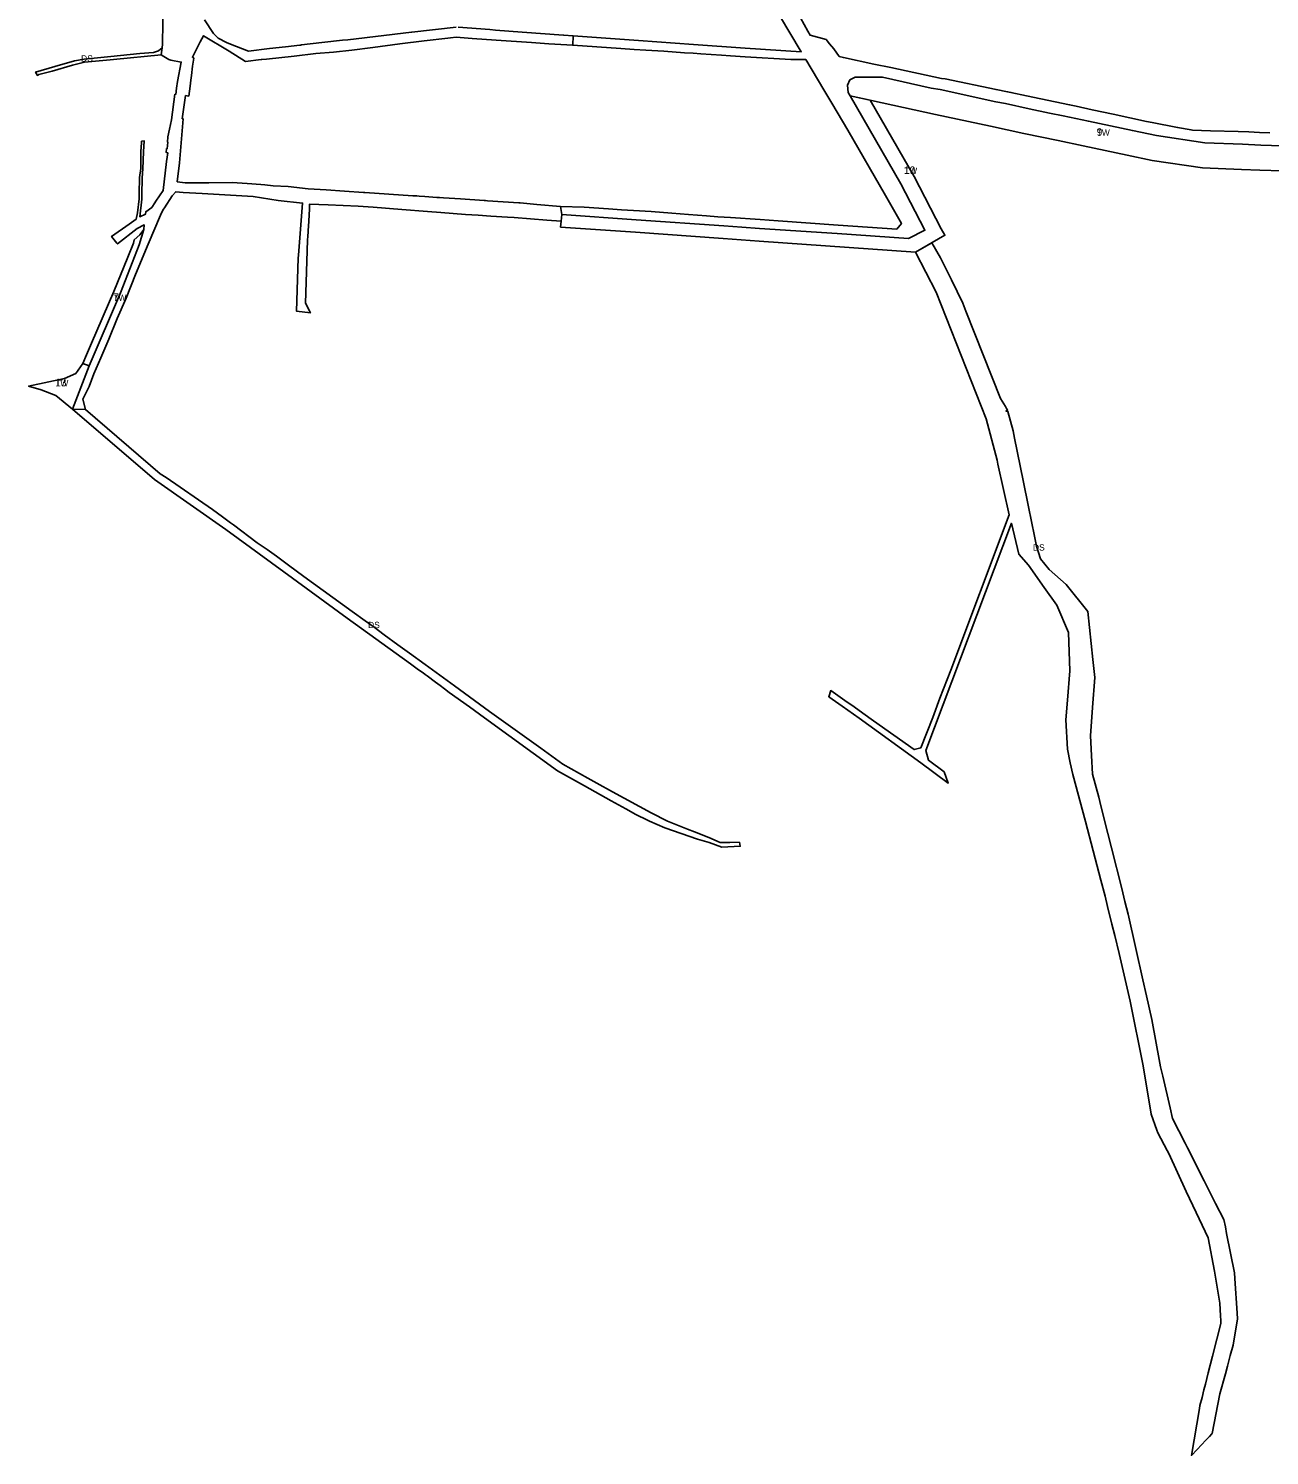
# Model space of a CAD drawing. Extents: x -540396 to -537847, y -1162344 to -1159959.
# Drawn here: x -540086 to -539100, y -1162344 to -1161210 of the extents above; entities that cross this region are included whole.
import ezdxf

# ---------------------------------------------------------------- set-up
doc = ezdxf.new("R2010")
doc.units = 0
for name, color, linetype in [('90320013', 7, 'Continuous'), ('90390023', 7, 'Continuous'), ('90450013', 7, 'Continuous'), ('ID_navrh', 7, 'Continuous')]:
    doc.layers.add(name, color=color, linetype=linetype)

msp = doc.modelspace()

# ---------------------------------------------------------------- linework, layer by layer
at = {"layer": '90320013'}
for points in [[(-539089.91, -1161303.49), (-539106.85, -1161302.97), (-539121.44, -1161302.27), (-539151.41, -1161301.15), (-539189.79, -1161295.41), (-539208.93, -1161291.41), (-539243.86, -1161284.07), (-539263.85, -1161279.74), (-539274.89, -1161277.57), (-539291.06, -1161274.07), (-539309.77, -1161269.96), (-539317.48, -1161268.47), (-539361.55, -1161258.93), (-539368.8, -1161257.67), (-539407.44, -1161249.02), (-539429.24, -1161248.96), (-539433.29, -1161251.13), (-539435.27, -1161255.47), (-539434.61, -1161261.23), (-539433.149, -1161263.76), (-539392.78, -1161333.67), (-539373.745, -1161370.579), (-539386.7, -1161377.26), (-539443.35, -1161373.22), (-539505.051, -1161369.199), (-539519.3, -1161368.27), (-539533.39, -1161367.17), (-539603.07, -1161362.24), (-539662.27, -1161358.06), (-539663.28, -1161351.67), (-539644.31, -1161352.21), (-539625.23, -1161353.54), (-539614.66, -1161354.26), (-539605.28, -1161354.9), (-539591.1, -1161355.75), (-539574.79, -1161357.02), (-539561.62, -1161358.04), (-539547.15, -1161359.17), (-539538.26, -1161359.87), (-539528.28, -1161360.42), (-539504.725, -1161362.116), (-539490.23, -1161363.16), (-539442.69, -1161366.45), (-539396.15, -1161369.7), (-539392.4, -1161365.24), (-539405.14, -1161343.09), (-539434.98, -1161291.19), (-539447.73, -1161269.69), (-539453.999, -1161259.118), (-539468.39, -1161234.85), (-539480.24, -1161235.04), (-539516.42, -1161232.77), (-539528.25, -1161232.02), (-539535.3, -1161231.55), (-539551.82, -1161230.45), (-539557.83, -1161230.05), (-539564.86, -1161229.58), (-539581.18, -1161228.48), (-539595.35, -1161227.56), (-539604.73, -1161226.91), (-539615.3, -1161226.19), (-539634.26, -1161224.84), (-539653.53, -1161223.65), (-539653.3, -1161216.096), (-539601.36, -1161219.9), (-539557.69, -1161223.11), (-539516.59, -1161225.93), (-539472.01, -1161228.75), (-539497.36, -1161186)], [(-539481.41, -1161185.77), (-539466.8, -1161212.37), (-539464.98, -1161215.56), (-539452.22, -1161219.18), (-539449.58, -1161222.58), (-539446.12, -1161226.55), (-539441.79, -1161232.59), (-539438.49, -1161233.39), (-539414.3, -1161238.64), (-539400.77, -1161241.37), (-539360.48, -1161249.96), (-539357.66, -1161250.4), (-539317.28, -1161258.8), (-539308.15, -1161260.59), (-539305.49, -1161261.12), (-539293.08, -1161263.8), (-539258.85, -1161270.91), (-539253.51, -1161272.15), (-539240.79, -1161274.83), (-539224.32, -1161278.28), (-539197.72, -1161284.19), (-539193.16, -1161285.12), (-539173.01, -1161288.87), (-539162.36, -1161290.96), (-539161.16, -1161290.98), (-539146.97, -1161291.52), (-539124.88, -1161292.22), (-539116.49, -1161292.48), (-539108, -1161292.84), (-539099.9, -1161293.1)]]:
    msp.add_lwpolyline(points, dxfattribs=at)
for points in [[(-539980.37, -1161231.37), (-540018.19, -1161235.06), (-540020.9, -1161235.32), (-540041.25, -1161236.99), (-540050.81, -1161239.42), (-540066.97, -1161244.16), (-540077.53, -1161246.89), (-540078.75, -1161247.62), (-540080.23, -1161245.02), (-540064.95, -1161240.41), (-540049.27, -1161236.06), (-540041.69, -1161234.71), (-540020.4, -1161232.66), (-539997.46, -1161230.27), (-539986.45, -1161229.39), (-539982.61, -1161228.15), (-539979.69, -1161225.62)], [(-539157.48, -1162338.86), (-539162.08, -1162343.72), (-539155.74, -1162306.54), (-539155.31, -1162303.99), (-539153.63, -1162297.71), (-539152.14, -1162291.59), (-539151, -1162287.13), (-539148.72, -1162278.22), (-539145.31, -1162264.9), (-539141.87, -1162251.48), (-539138.64, -1162238.84), (-539138.77, -1162236.64), (-539138.99, -1162232.85), (-539139.57, -1162222.82), (-539142.44, -1162205.39), (-539143.8, -1162197.43), (-539148.72, -1162171), (-539158.34, -1162150.83), (-539166.2, -1162134.06), (-539180.01, -1162104.01), (-539181.321, -1162101.563), (-539188.8, -1162087.6), (-539189.627, -1162085.25), (-539194.04, -1162072.72), (-539200.52, -1162034.32), (-539210.77, -1161982.93), (-539219.35, -1161944.98), (-539222.91, -1161930.72), (-539225.42, -1161921.81), (-539228.65, -1161907.73), (-539230.64, -1161899.55), (-539234.16, -1161886.78), (-539246.32, -1161840.14), (-539256.35, -1161802.83), (-539258.35, -1161793.49), (-539260.63, -1161782.68), (-539261.83, -1161759.51), (-539260.49, -1161743.77), (-539258.67, -1161720.64), (-539259.73, -1161690.18), (-539269.09, -1161668.45), (-539279.15, -1161654.33), (-539291.45, -1161636.72), (-539299.04, -1161627.81), (-539305.07, -1161603.34), (-539373.09, -1161783.93), (-539371.01, -1161791.56), (-539358.35, -1161800.84), (-539355.34, -1161809.82), (-539376.97, -1161793.72), (-539426, -1161758.14), (-539439.41, -1161748.71), (-539450.22, -1161741.11), (-539448.59, -1161736.16), (-539437.27, -1161744.18), (-539430.1, -1161749.19), (-539423.02, -1161754.26), (-539414.57, -1161760.24), (-539382.26, -1161783.08), (-539377.06, -1161781.74), (-539367.57, -1161757.57), (-539361.86, -1161742.26), (-539353.29, -1161719.96), (-539306.78, -1161596.54), (-539315.76, -1161556.43), (-539316.47, -1161553.16), (-539325.02, -1161520.27), (-539364.89, -1161419.69), (-539381.181, -1161387.997), (-539368.278, -1161380.57), (-539368.278, -1161380.57), (-539361.37, -1161392.57), (-539352.75, -1161410.03), (-539343.67, -1161428.41), (-539341.16, -1161434.73), (-539313.61, -1161504.16), (-539309.76, -1161510.68), (-539308.92, -1161512.11), (-539308.09, -1161513.51), (-539309.47, -1161514.21), (-539307.78, -1161514.67), (-539303.69, -1161529.93), (-539302.55, -1161535.61), (-539295.77, -1161569.23), (-539291.53, -1161590.26), (-539286.85, -1161613.44), (-539285.25, -1161621.38), (-539281.97, -1161631.64), (-539275.02, -1161640.13), (-539261.46, -1161651.91), (-539244.42, -1161673.52), (-539240.34, -1161711.55), (-539238.81, -1161725.75), (-539240.64, -1161749.54), (-539242.37, -1161772.11), (-539241.52, -1161787.71), (-539240.72, -1161802.49), (-539235.74, -1161820.78), (-539234.86, -1161824.29), (-539231.34, -1161838.25), (-539225.57, -1161861.14), (-539217.45, -1161893.33), (-539214.84, -1161903.7), (-539212.32, -1161913.69), (-539206.22, -1161940.94), (-539200.6, -1161966.02), (-539197.76, -1161978.7), (-539193.59, -1161997.34), (-539187.18, -1162032.19), (-539186.67, -1162034.94), (-539184.9, -1162042.56), (-539179.07, -1162067.59), (-539177.1, -1162076.06), (-539167.17, -1162095.62), (-539165.27, -1162099.36), (-539151.92, -1162125.67), (-539142.82, -1162143.59), (-539136.3, -1162156.43), (-539135.1, -1162162.18), (-539134.14, -1162167.31), (-539127.98, -1162198.77), (-539127.7, -1162203.08), (-539125.86, -1162230.82), (-539125.58, -1162235.11), (-539128.98, -1162256.1), (-539131.26, -1162264.39), (-539133.55, -1162272.74), (-539135.12, -1162278.84), (-539139.62, -1162294.87), (-539145.6, -1162326.2), (-539145.63, -1162326.35), (-539145.93, -1162326.67), (-539147.73, -1162328.57), (-539150.57, -1162331.57)], [(-539521.049, -1161856.579), (-539520.5, -1161859.91), (-539535.16, -1161860.62), (-539535.16, -1161860.62), (-539545.25, -1161856.85), (-539554.51, -1161854.21), (-539580.36, -1161845.31), (-539592.43, -1161840.03), (-539594.06, -1161839.24), (-539603.34, -1161834.57), (-539611.45, -1161830.1), (-539622.87, -1161823.86), (-539644.29, -1161811.93), (-539665.66, -1161800.04), (-539723.58, -1161757.8), (-539735.61, -1161749.14), (-539751.72, -1161737.63), (-539755.49, -1161734.76), (-539758.86, -1161732.11), (-539762.51, -1161729.49), (-539769.25, -1161724.43), (-539770.71, -1161723.36), (-539772.29, -1161722.22), (-539775.92, -1161719.61), (-539782.3, -1161715.02), (-539832.65, -1161678.79), (-539882.99, -1161642.02), (-539929.16, -1161608.15), (-539985.72, -1161568.53), (-540050.98, -1161512.57), (-540040.55, -1161513.09), (-539981.13, -1161564.01), (-539976.59, -1161567.1), (-539939.69, -1161592.41), (-539931.76, -1161598.16), (-539925.41, -1161603.03), (-539923.06, -1161604.56), (-539904.11, -1161618.82), (-539896.23, -1161624.24), (-539888.88, -1161629.56), (-539879.18, -1161636.73), (-539867.18, -1161645.5), (-539828.73, -1161673.29), (-539818.4, -1161680.77), (-539811.18, -1161685.91), (-539803.22, -1161692.04), (-539792.51, -1161699.77), (-539783.08, -1161706.4), (-539770.78, -1161715.47), (-539747.55, -1161732.32), (-539719.52, -1161752.83), (-539678.99, -1161782.08), (-539661.42, -1161794.73), (-539641.65, -1161805.83), (-539634.29, -1161809.82), (-539621.96, -1161816.51), (-539591.16, -1161833.38), (-539578.2, -1161839.8), (-539562.42, -1161846.2), (-539556.8, -1161848.47), (-539545.54, -1161853.03), (-539536.48, -1161856.9), (-539530.99, -1161856.83), (-539528.75, -1161856.77)]]:
    msp.add_lwpolyline(points, close=True, dxfattribs=at)
at = {"layer": '90390023'}
msp.add_lwpolyline([(-539089.891, -1161323.5), (-539107.636, -1161322.955), (-539122.293, -1161322.252), (-539153.268, -1161321.094), (-539193.318, -1161315.105), (-539213.032, -1161310.985), (-539248.033, -1161303.63), (-539267.896, -1161299.327), (-539295.249, -1161293.626), (-539321.669, -1161288.026), (-539365.38, -1161278.564), (-539433.149, -1161263.76), (-539434.61, -1161261.23), (-539435.27, -1161255.47), (-539433.29, -1161251.13), (-539429.24, -1161248.96), (-539407.44, -1161249.02), (-539368.8, -1161257.67), (-539361.55, -1161258.93), (-539317.48, -1161268.47), (-539309.77, -1161269.96), (-539291.06, -1161274.07), (-539274.89, -1161277.57), (-539263.85, -1161279.74), (-539243.86, -1161284.07), (-539208.93, -1161291.41), (-539189.79, -1161295.41), (-539151.41, -1161301.15), (-539121.44, -1161302.27), (-539106.85, -1161302.97), (-539089.91, -1161303.49)], dxfattribs=at)
for points in [[(-539392.78, -1161333.67), (-539433.149, -1161263.76), (-539417.292, -1161267.224), (-539382.245, -1161327.916), (-539360.762, -1161369.573), (-539357.878, -1161374.583), (-539381.181, -1161387.997), (-539381.181, -1161387.997), (-539505.512, -1161379.19), (-539534.132, -1161377.143), (-539603.775, -1161372.215), (-539663.153, -1161368.023), (-539662.82, -1161363.31), (-539662.27, -1161358.06), (-539603.07, -1161362.24), (-539533.39, -1161367.17), (-539533.39, -1161367.17), (-539519.3, -1161368.27), (-539505.051, -1161369.199), (-539443.35, -1161373.22), (-539386.7, -1161377.26), (-539373.745, -1161370.579)], [(-540037.71, -1161478.38), (-540042.66, -1161476.53), (-540039.63, -1161469.45), (-540035.68, -1161460.26), (-540018.07, -1161419.18), (-540006.87, -1161392.1), (-540002.48, -1161380.93), (-540001.8, -1161378.25), (-539997.48, -1161374.21), (-539994.23, -1161370.06), (-539997.87, -1161382.24), (-540012.81, -1161420.17)], [(-540050.98, -1161512.57), (-540064.03, -1161501.76), (-540075.88, -1161497.34), (-540085.79, -1161494.36), (-540057.1, -1161488.42), (-540048.26, -1161484.24), (-540042.66, -1161476.53), (-540037.71, -1161478.38)]]:
    msp.add_lwpolyline(points, close=True, dxfattribs=at)
at = {"layer": '90450013'}
for points in [[(-539744.56, -1161209.39), (-539719.26, -1161211.25), (-539714.87, -1161211.57), (-539693.56, -1161213.36), (-539660.82, -1161215.54), (-539660.8, -1161215.562), (-539653.3, -1161216.096), (-539653.53, -1161223.65), (-539672.51, -1161222.45), (-539686.21, -1161221.43), (-539714.29, -1161219.59), (-539733.34, -1161218.34), (-539746, -1161217.27), (-539750.72, -1161217.77), (-539752.74, -1161217.98), (-539771.56, -1161220.17), (-539790.88, -1161222.4), (-539812.32, -1161225.45), (-539829.01, -1161227.48), (-539843.55, -1161229.12), (-539857.67, -1161230.15), (-539874.84, -1161232.25), (-539896.77, -1161234.72), (-539900.48, -1161234.96), (-539901.02, -1161235.02), (-539913.51, -1161236.43), (-539926.55, -1161228.46), (-539946.77, -1161216.07), (-539949.55, -1161220.81), (-539955.58, -1161233.13), (-539954.5, -1161233.86), (-539955.43, -1161240.24), (-539956.37, -1161247.57), (-539956.87, -1161251.38), (-539957.47, -1161256.04), (-539958.49, -1161264.01), (-539961.06, -1161263.65), (-539963.64, -1161282.05), (-539962.89, -1161282.14), (-539965.8, -1161317.02), (-539967.7, -1161332.12), (-539961.26, -1161332.92), (-539942.51, -1161332.83), (-539924.12, -1161332.74), (-539912.03, -1161333.59), (-539901.28, -1161334.35), (-539897.98, -1161334.58), (-539891.53, -1161335.2), (-539879.56, -1161335.87), (-539863.79, -1161337.58), (-539849.31, -1161338.54), (-539834.7, -1161339.57), (-539819.59, -1161340.58), (-539818.54, -1161340.65), (-539799.67, -1161341.99), (-539780.63, -1161343.3), (-539777.4, -1161343.34), (-539775.61, -1161343.4), (-539771.1, -1161343.91), (-539761.35, -1161344.54), (-539759.35, -1161344.67), (-539756.16, -1161344.87), (-539742.71, -1161345.74), (-539723.76, -1161346.96), (-539722.83, -1161347.02), (-539721.32, -1161347.12), (-539696.26, -1161348.73), (-539695.82, -1161348.76), (-539695.38, -1161348.81), (-539682.12, -1161350.21), (-539663.28, -1161351.67), (-539662.27, -1161358.06), (-539662.82, -1161363.31), (-539673.99, -1161362.5), (-539699.97, -1161360.59), (-539705.21, -1161360.27), (-539718.68, -1161359.3), (-539728.61, -1161358.63), (-539738.63, -1161357.96), (-539748.61, -1161357.23), (-539758.37, -1161356.36), (-539768.76, -1161355.61), (-539789.34, -1161354.12), (-539811.97, -1161352.35), (-539820.04, -1161351.68), (-539823.93, -1161351.43), (-539835.92, -1161350.96), (-539847.84, -1161350.4), (-539862.58, -1161349.75), (-539862.73, -1161353.71), (-539863.08, -1161363.31), (-539863.69, -1161370.95), (-539863.75, -1161371.76), (-539863.94, -1161375.33), (-539864.11, -1161378.56), (-539865.67, -1161428.44), (-539861.95, -1161436.3), (-539872.87, -1161434.88), (-539871.55, -1161392.64), (-539871.36, -1161390.27), (-539868.11, -1161348.99), (-539887.44, -1161346.86), (-539907.34, -1161343.79), (-539947.99, -1161341.3), (-539962.92, -1161340.72), (-539968.86, -1161340.01), (-539971.64, -1161343.16), (-539977.82, -1161352.71), (-539978.64, -1161353.97), (-539979.41, -1161355.16), (-539980.9, -1161358.74), (-539990.65, -1161381.75), (-540000.81, -1161405.7), (-540008.35, -1161424.63), (-540015.28, -1161440.63), (-540022.1, -1161457.12), (-540028.39, -1161471.99), (-540033.82, -1161484.55), (-540037.74, -1161494.78), (-540042.61, -1161504.68), (-540040.55, -1161513.09), (-540050.98, -1161512.57), (-540037.71, -1161478.38), (-540012.81, -1161420.17), (-539997.87, -1161382.24), (-539994.23, -1161370.06), (-539993.83, -1161366.31), (-539999.44, -1161369.08), (-540015.115, -1161381.443), (-540015.659, -1161380.753), (-540019.81, -1161375.49), (-540005.96, -1161365.88), (-540000.37, -1161361.86), (-539999.33, -1161356.66), (-539997.96, -1161345.66), (-539997.9, -1161343.27), (-539997.85, -1161341.5), (-539997.52, -1161328.72), (-539996.7, -1161321.56), (-539996.61, -1161308.12), (-539996.01, -1161301.19), (-539995.94, -1161299.88), (-539993.82, -1161299.61), (-539994.48, -1161308.21), (-539994.93, -1161321.76), (-539995.6, -1161328.93), (-539995.8, -1161342.48), (-539995.82, -1161344), (-539995.85, -1161345.83), (-539997.43, -1161359.85), (-539992.93, -1161357.91), (-539992.72, -1161355.93), (-539987.98, -1161352.48), (-539985.49, -1161348.83), (-539984.64, -1161347.58), (-539978.77, -1161338.94), (-539976.1, -1161316.04), (-539975.17, -1161309), (-539976.56, -1161308.82), (-539976.15, -1161305.75), (-539975.76, -1161305.8), (-539975.13, -1161300.74), (-539975.52, -1161300.58), (-539975.02, -1161296.31), (-539973.84, -1161290.43), (-539972.32, -1161282.82), (-539969.68, -1161262.61), (-539968.88, -1161262.69), (-539968.19, -1161257.77), (-539967.45, -1161252.53), (-539964.53, -1161237.08), (-539972.76, -1161235.41), (-539974.35, -1161234.92), (-539978.192, -1161232.655), (-539980.37, -1161231.37), (-539979.69, -1161225.62), (-539979.34, -1161222.69), (-539978.91, -1161188.87)], [(-539946.14, -1161203.53), (-539938.93, -1161214.23), (-539935.07, -1161217.96), (-539928.62, -1161221.45), (-539925.44, -1161222.83), (-539911.02, -1161228.47), (-539894.49, -1161226.3), (-539881.78, -1161224.84), (-539870.22, -1161223.63), (-539869.84, -1161223.54), (-539868.95, -1161223.44), (-539852.69, -1161221.575), (-539836.43, -1161219.71), (-539832.19, -1161219.23), (-539781.63, -1161213.38), (-539781.34, -1161213.37), (-539745.98, -1161209.27)]]:
    msp.add_lwpolyline(points, dxfattribs=at)

# ---------------------------------------------------------------- texts
at = {"layer": '90320013'}
for p in [(-540044.015, -1161236.62), (-539287.9, -1161625.021), (-539816.047, -1161686.595)]:
    msp.add_text('DS', height=5, rotation=360, dxfattribs=at).set_placement(p)
at = {"layer": '90390023'}
for rotation, p in [(360, (-539237.324, -1161295.569)), (0, (-539390.35, -1161325.879)), (360, (-540018.445, -1161426.699)), (0, (-540064.572, -1161494.55))]:
    msp.add_text('TW', height=5, rotation=rotation, dxfattribs=at).set_placement(p)
at = {"layer": 'ID_navrh'}
for s, rotation, p in [('9', 0, (-539237.324, -1161295.569)), ('10', 0, (-539390.35, -1161325.879)), ('7', 360, (-540018.445, -1161426.699)), ('13', 360, (-540064.572, -1161494.55))]:
    msp.add_text(s, height=6, rotation=rotation, dxfattribs=at).set_placement(p)

doc.saveas('drawing.dxf')
